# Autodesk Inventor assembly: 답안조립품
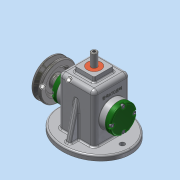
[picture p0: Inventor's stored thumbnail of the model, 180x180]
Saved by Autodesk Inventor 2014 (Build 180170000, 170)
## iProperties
Created: 2017-07
Part Number: 답안조립품
Document SubType Name: Assembly
Designer: 702-11
Author: 702-11
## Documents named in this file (16)
- C:\Users\702-11\Desktop\470708V1021\답안조립품.iam
- C:\Users\702-11\Desktop\470708V1021\본체.ipt
- C:\Users\702-11\Desktop\470708V1021\앞커버.ipt
- C:\Users\702-11\Desktop\470708V1021\뒤커버.ipt
- C:\Users\702-11\Desktop\470708V1021\베어링 12 x 32 x 10.ipt
- C:\Users\702-11\Desktop\470708V1021\편심축.ipt
- C:\Users\702-11\Desktop\470708V1021\링크.ipt
- C:\Users\702-11\Desktop\470708V1021\볼트 M4 x 12.ipt
- C:\Users\702-11\Desktop\470708V1021\오일실 12 25 7.ipt
- C:\Users\702-11\Desktop\470708V1021\키 4 x 4 x 10.ipt
- C:\Users\702-11\Desktop\470708V1021\V벨트풀리.ipt
- C:\Users\702-11\Desktop\470708V1021\멈춤나사 M3x8.ipt
- C:\Users\702-11\Desktop\470708V1021\핀 5 x 18.ipt
- C:\Users\702-11\Desktop\470708V1021\고정핀 1.2 x  8.ipt
- C:\Users\702-11\Desktop\470708V1021\부시.ipt
- C:\Users\702-11\Desktop\470708V1021\슬라이드.ipt
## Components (3 placed, 3 different names)
1. V벨트풀리:1
2. 핀 5 x 18:1 — 플러쉬:6
3. 고정핀 1.2 x  8:1
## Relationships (1: Flush 1)
- 플러쉬:6 [Flush]: 핀 5 x 18:1
